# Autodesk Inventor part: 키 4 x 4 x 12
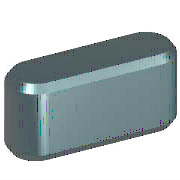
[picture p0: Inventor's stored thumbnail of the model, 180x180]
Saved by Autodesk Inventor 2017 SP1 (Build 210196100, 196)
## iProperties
IsCustomPart: 1
Created: 2012-02
Part Number: 키 4 x 4 x 12
Material: 강철, 연강
Description: 키 및 해당 키홈
Document SubType Name: Modeling
Standard: KS B 1311
Designer: mduedu
Standards Organization: KS
Language: ko-KR
Size Designation: 4 x 4 x 12
Categories: <MemberInstance><Categories><Category DisplayName="샤프트 부품" InternalName="7f7aeb1f-a693-4053-b835-cee3144e0d98" Mnemonic="SHFT"><Category DisplayName="키" Interna
Density: 1 g/cm^3
Appearance: 노란색
Author: mduedu
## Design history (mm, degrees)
workplane "Work Plane1"
workplane "Work Plane2"
sketch "스케치1"
  geometry: L1 (2, 2)-(10, 2); L2 (10, -2)-(2, -2); L3 (0, 9.4)-(0, -7.4) reference; L4 (-5, 0)-(30, 0) reference; L5 (12, 0)-(12, 7); A1 r 2 centre (2, 0) between (2, 2) and (2, -2); A2 r 2 centre (10, 0) between (10, -2) and (10, 2)
  constraints: 6 end point, 5 point on circle, 4 tangent, 3 point on line, 2 centre point, 1 horizontal, 1 parallel, 1 perpendicular
  dimensions: "d0" = 2 radius of A1 (= 0.5 x PB); "d13" = 2 radius of A2 (= 0.5 x PB); "d14" = 12 distance between parallel lines of L5 L3 (= NLG)
extrude "본체1" new body sketch "스케치1" taper "d3" = 0 deg; stored distance "d4" = 10
workplane "Work Plane3"
body "Solid1"
chamfer "모따기1" distance "d8" = 0.25 (= PHH); stored, may be unused: second distance "d9" = 0.25 (= PHH), angle "d15" = 45 deg
other parameters: "d1" = -2.5 (= -PNT), "d2" = 1.5 (= PH - PNT), "NLG" = 12 [user parameter; used in 3 equation terms], "PB" = 4 [user parameter; used in 2 equation terms], "PNT" = 2.5 [user parameter; used in 2 equation terms], "PH" = 4 [user parameter; used in 1 equation term], "PHH" = 0.25 [user parameter; used in 2 equation terms], "d10" = 0, "d16" = 0, "d17" = 0, "d18" = 0, "PLB2" = 12 (= NLG) [user parameter], "WDMAX" = 12 [user parameter], "PLB1" = 12 (= NLG) [user parameter], "RR" = 0.08 [user parameter], "PUEB" = 1.8 [user parameter]
